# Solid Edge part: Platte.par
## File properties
Sűrűség: 0,000 kg/m^3
Pontosság: 0,990
Author: bmolnar
Last saved by: bmolnar
Revision: 76
Username: bmolnar
Dokumentum tartalom típus: 0
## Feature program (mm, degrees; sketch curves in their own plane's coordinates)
base feature "unnamed BaseFeature 1"
thread "unnamed Thread 1"
thread "unnamed Thread 2"
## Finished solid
Body 1: solid body, 65 faces, 114 edges, 88 vertices.
  Faces by surface: plane 38, cylinder 12, cone 10, torus 5
  Edges by curve: line 60, circle 36, spline 18
Bounding box of the edges (mm; curved faces can reach further): 85.000 x 30.000 x 12.000, from (-42.5, -15, 0) to (42.5, 15, 12).
Cylindrical faces by radius (mm): R2 x2, R2.25 x2, R2.4585 x2, R3.5 x2, R4 x2, R6.5 x1, R11 x1
Conical faces (half-angle, radius in mm at the cone's reference point): 45 deg R2.35 x2, 45 deg R2.9585 x4, 45 deg R11.25 x1, 60 deg R1 x2, 60 deg R1.4434 x1
Toroidal faces (ring radius, tube radius in mm): R2.1 r0.1 x2, R3.1 r0.4 x2, R5.7 r0.8 x1
Planar faces by outward normal: +x 1, +y 4, +z 7, -x 1, -y 4, -z 5, oblique 16
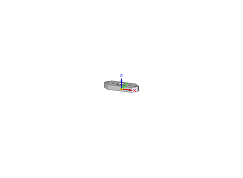
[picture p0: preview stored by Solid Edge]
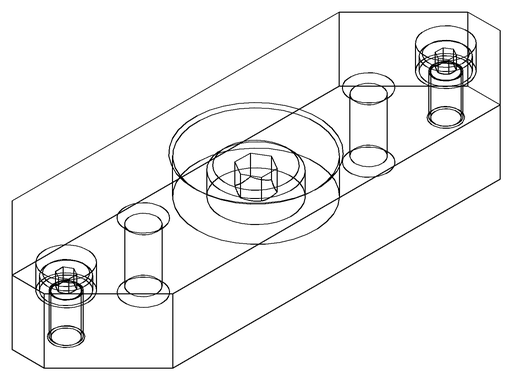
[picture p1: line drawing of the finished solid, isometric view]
